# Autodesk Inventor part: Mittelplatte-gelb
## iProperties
Created: 2004-10
Part Number: Mittelplatte-gelb
Document SubType Name: Modeling
Designer: sahrens
Manufacturer: Standard
Standards Organization: Custom
Author: sahrens
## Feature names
1. Extrusion1
2. Extrusion2
3. Rundung2 [Fillet]
